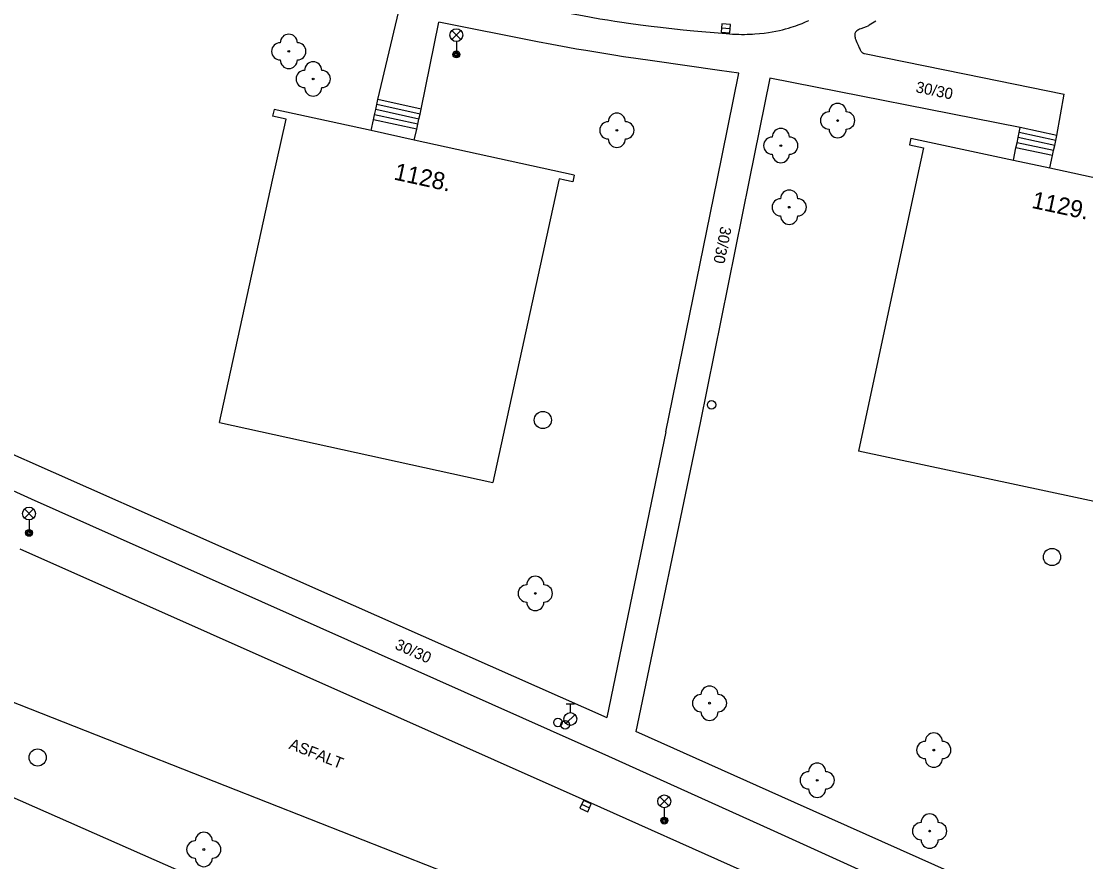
# Model space of a CAD drawing. Extents: x -538441 to -536770, y -1181008 to -1179809.
# Drawn here: x -538284.9 to -538222.9, y -1180822.8 to -1180773.9 of the extents above; entities that cross this region are included whole.
import ezdxf

# ---------------------------------------------------------------- set-up
doc = ezdxf.new("R2010")
doc.units = 0
for name, color, linetype in [('Vrstva 10', 7, 'Continuous'), ('Vrstva 11', 7, 'Continuous'), ('Vrstva 22', 7, 'Continuous'), ('Vrstva 27', 7, 'Continuous'), ('Vrstva 28', 7, 'Continuous'), ('Vrstva 33', 7, 'Continuous'), ('Vrstva 40', 7, 'Continuous'), ('Vrstva 47', 7, 'Continuous'), ('Vrstva 5', 7, 'Continuous')]:
    doc.layers.add(name, color=color, linetype=linetype)

msp = doc.modelspace()

# ---------------------------------------------------------------- linework, layer by layer
at = {"layer": 'Vrstva 10'}
for p, q in [((-538249.548, -1180773.977), (-538248.837, -1180774.075)), ((-538284.99, -1180804.6), (-538268.454, -1180811.952)), ((-538277.975, -1180816.445), (-538297.92, -1180808.6)), ((-538268.454, -1180811.952), (-538251.92, -1180819.31)), ((-538258.03, -1180824.29), (-538277.975, -1180816.445)), ((-538251.92, -1180819.31), (-538242.888, -1180823.336))]:
    msp.add_line(p, q, dxfattribs=at)
for points in [[(-538258.788, -1180772.341), (-538258.382, -1180772.429), (-538258.001, -1180772.508), (-538257.642, -1180772.58), (-538256.969, -1180772.709), (-538256.379, -1180772.817), (-538255.343, -1180772.998), (-538253.787, -1180773.264), (-538253.008, -1180773.399), (-538252.23, -1180773.54), (-538251.709, -1180773.634), (-538251.22, -1180773.719), (-538250.761, -1180773.794), (-538250.331, -1180773.862), (-538249.927, -1180773.923), (-538249.548, -1180773.977)], [(-538248.837, -1180774.075), (-538248.215, -1180774.155), (-538247.671, -1180774.22), (-538247.194, -1180774.275), (-538246.36, -1180774.364), (-538245.734, -1180774.426), (-538245.266, -1180774.47), (-538244.562, -1180774.532), (-538243.86, -1180774.59), (-538243.666, -1180774.604), (-538243.479, -1180774.615), (-538243.298, -1180774.623), (-538243.122, -1180774.628), (-538242.953, -1180774.63), (-538242.788, -1180774.63), (-538242.629, -1180774.627), (-538242.475, -1180774.623), (-538242.326, -1180774.616), (-538242.182, -1180774.607), (-538241.903, -1180774.585), (-538241.642, -1180774.557), (-538241.397, -1180774.524), (-538241.168, -1180774.486), (-538240.954, -1180774.446), (-538240.754, -1180774.403), (-538240.566, -1180774.359), (-538240.39, -1180774.313), (-538240.226, -1180774.267), (-538240.072, -1180774.22), (-538239.928, -1180774.173), (-538239.793, -1180774.127), (-538239.667, -1180774.081), (-538239.43, -1180773.99), (-538239.223, -1180773.903), (-538239.043, -1180773.821)]]:
    msp.add_lwpolyline(points, dxfattribs=at)
at = {"layer": 'Vrstva 11'}
for p, q in [((-538264.14, -1180778.43), (-538262.92, -1180773.28)), ((-538261.622, -1180778.982), (-538260.6, -1180773.92)), ((-538254.838, -1180775.066), (-538260.6, -1180773.92)), ((-538235.8, -1180775.75), (-538229.98, -1180776.935)), ((-538244.387, -1180783.117), (-538243.12, -1180776.89)), ((-538241.31, -1180777.19), (-538242.506, -1180783.117)), ((-538226.72, -1180780.06), (-538241.31, -1180777.19)), ((-538229.98, -1180776.935), (-538224.16, -1180778.12)), ((-538261.622, -1180778.982), (-538264.14, -1180778.43)), ((-538224.593, -1180780.515), (-538224.16, -1180778.12)), ((-538261.75, -1180779.568), (-538264.268, -1180779.016)), ((-538261.686, -1180779.275), (-538264.204, -1180778.723)), ((-538261.878, -1180780.154), (-538264.396, -1180779.602)), ((-538261.814, -1180779.861), (-538264.332, -1180779.309)), ((-538224.593, -1180780.515), (-538226.72, -1180780.06)), ((-538224.781, -1180781.395), (-538226.908, -1180780.94)), ((-538224.718, -1180781.101), (-538226.845, -1180780.646)), ((-538224.655, -1180780.808), (-538226.782, -1180780.353)), ((-538224.844, -1180781.688), (-538226.971, -1180781.233)), ((-538247.37, -1180797.77), (-538244.387, -1180783.117)), ((-538242.506, -1180783.117), (-538245.36, -1180797.26)), ((-538296.641, -1180794.101), (-538283.06, -1180800.13)), ((-538296.73, -1180796.15), (-538284.33, -1180801.67)), ((-538245.36, -1180797.26), (-538249.11, -1180815.22)), ((-538247.37, -1180797.77), (-538250.81, -1180814.42)), ((-538283.06, -1180800.13), (-538266.936, -1180807.277)), ((-538284.33, -1180801.67), (-538267.518, -1180809.165)), ((-538266.936, -1180807.277), (-538250.81, -1180814.42)), ((-538267.518, -1180809.165), (-538250.71, -1180816.67)), ((-538239.865, -1180819.36), (-538249.11, -1180815.22)), ((-538250.71, -1180816.67), (-538241.284, -1180820.915)), ((-538230.62, -1180823.5), (-538239.865, -1180819.36)), ((-538241.284, -1180820.915), (-538231.87, -1180825.19))]:
    msp.add_line(p, q, dxfattribs=at)
for points in [[(-538235.562, -1180774.13), (-538235.606, -1180774.153), (-538235.693, -1180774.191), (-538236.011, -1180774.303), (-538236.088, -1180774.335), (-538236.143, -1180774.362), (-538236.182, -1180774.385), (-538236.238, -1180774.424), (-538236.265, -1180774.446), (-538236.29, -1180774.47), (-538236.318, -1180774.504), (-538236.338, -1180774.538), (-538236.351, -1180774.573), (-538236.36, -1180774.607)], [(-538235.134, -1180773.862), (-538235.327, -1180773.981), (-538235.517, -1180774.103), (-538235.562, -1180774.13)], [(-538236.36, -1180774.607), (-538236.364, -1180774.64), (-538236.365, -1180774.672), (-538236.364, -1180774.704), (-538236.357, -1180774.763), (-538236.346, -1180774.817), (-538236.333, -1180774.865), (-538236.304, -1180774.948), (-538236.28, -1180775.009), (-538236.24, -1180775.098), (-538236.22, -1180775.14), (-538236.2, -1180775.18), (-538236.162, -1180775.263), (-538236.097, -1180775.419), (-538236.071, -1180775.476), (-538236.047, -1180775.525), (-538236.024, -1180775.566), (-538236.003, -1180775.599), (-538235.983, -1180775.627), (-538235.945, -1180775.67), (-538235.913, -1180775.698), (-538235.888, -1180775.715), (-538235.868, -1180775.727), (-538235.835, -1180775.74), (-538235.8, -1180775.75)], [(-538252.567, -1180775.487), (-538253.071, -1180775.397), (-538254.014, -1180775.223), (-538254.838, -1180775.066)], [(-538243.12, -1180776.89), (-538244.234, -1180776.729), (-538248.137, -1180776.181), (-538249.111, -1180776.04), (-538249.842, -1180775.931), (-538250.39, -1180775.846), (-538251.21, -1180775.716), (-538252.03, -1180775.58), (-538252.567, -1180775.487)], [(-538264.536, -1180780.238), (-538264.396, -1180779.602), (-538264.332, -1180779.309), (-538264.268, -1180779.016), (-538264.204, -1180778.723), (-538264.14, -1180778.43)], [(-538262.018, -1180780.79), (-538261.878, -1180780.154), (-538261.814, -1180779.861), (-538261.75, -1180779.568), (-538261.686, -1180779.275), (-538261.622, -1180778.982)], [(-538227.125, -1180781.956), (-538226.971, -1180781.233), (-538226.908, -1180780.94), (-538226.845, -1180780.646), (-538226.782, -1180780.353), (-538226.72, -1180780.06)], [(-538224.998, -1180782.411), (-538224.844, -1180781.688), (-538224.781, -1180781.395), (-538224.718, -1180781.101), (-538224.655, -1180780.808), (-538224.593, -1180780.515)]]:
    msp.add_lwpolyline(points, dxfattribs=at)
at = {"layer": 'Vrstva 22'}
for centre in [(-538269.33, -1180775.62), (-538267.91, -1180777.23), (-538237.36, -1180779.65), (-538250.22, -1180780.22), (-538240.67, -1180781.11), (-538240.18, -1180784.7), (-538254.97, -1180807.19), (-538244.82, -1180813.58), (-538231.76, -1180816.31), (-538238.55, -1180818.07), (-538232, -1180821.03), (-538274.28, -1180822.1)]:
    msp.add_circle(centre, 0.05, dxfattribs=at)
for centre, start, end in [((-538269.33, -1180775.12), 0, 180), ((-538269.83, -1180775.62), 90, 270), ((-538268.83, -1180775.62), 270, 90), ((-538269.33, -1180776.12), 180, 0), ((-538267.91, -1180776.73), 0, 180), ((-538268.41, -1180777.23), 90, 270), ((-538267.41, -1180777.23), 270, 90), ((-538267.91, -1180777.73), 180, 0), ((-538237.36, -1180779.15), 0, 180), ((-538250.22, -1180779.72), 0, 180), ((-538237.86, -1180779.65), 90, 270), ((-538236.86, -1180779.65), 270, 90), ((-538250.72, -1180780.22), 90, 270), ((-538249.72, -1180780.22), 270, 90), ((-538240.67, -1180780.61), 0, 180), ((-538237.36, -1180780.15), 180, 0), ((-538250.22, -1180780.72), 180, 0), ((-538241.17, -1180781.11), 90, 270), ((-538240.17, -1180781.11), 270, 90), ((-538240.67, -1180781.61), 180, 0), ((-538240.18, -1180784.2), 0, 180), ((-538240.68, -1180784.7), 90, 270), ((-538239.68, -1180784.7), 270, 90), ((-538240.18, -1180785.2), 180, 0), ((-538254.97, -1180806.69), 0, 180), ((-538255.47, -1180807.19), 90, 270), ((-538254.47, -1180807.19), 270, 90), ((-538254.97, -1180807.69), 180, 0), ((-538245.32, -1180813.58), 90, 270), ((-538244.82, -1180813.08), 0, 180), ((-538244.32, -1180813.58), 270, 90), ((-538244.82, -1180814.08), 180, 0), ((-538231.76, -1180815.81), 0, 180), ((-538232.26, -1180816.31), 90, 270), ((-538231.26, -1180816.31), 270, 90), ((-538231.76, -1180816.81), 180, 0), ((-538238.55, -1180817.57), 0, 180), ((-538239.05, -1180818.07), 90, 270), ((-538238.05, -1180818.07), 270, 90), ((-538238.55, -1180818.57), 180, 0), ((-538232.5, -1180821.03), 90, 270), ((-538232, -1180820.53), 0, 180), ((-538231.5, -1180821.03), 270, 90), ((-538274.28, -1180821.6), 0, 180), ((-538274.78, -1180822.1), 90, 270), ((-538273.78, -1180822.1), 270, 90), ((-538232, -1180821.53), 180, 0), ((-538274.28, -1180822.6), 180, 0)]:
    msp.add_arc(centre, 0.5, start, end, dxfattribs=at)
at = {"layer": 'Vrstva 27'}
for p, q in [((-538243.619, -1180774.3), (-538244.117, -1180774.262)), ((-538252.274, -1180819.467), (-538251.818, -1180819.671))]:
    msp.add_line(p, q, dxfattribs=at)
for points in [[(-538243.6, -1180774.051), (-538244.098, -1180774.013), (-538244.136, -1180774.511), (-538243.638, -1180774.549)], [(-538252.376, -1180819.696), (-538251.919, -1180819.899), (-538251.716, -1180819.442), (-538252.173, -1180819.239)]]:
    msp.add_lwpolyline(points, close=True, dxfattribs=at)
for centre in [(-538254.53, -1180797.09), (-538224.87, -1180805.07), (-538283.96, -1180816.74)]:
    msp.add_circle(centre, 0.5, dxfattribs=at)
at = {"layer": 'Vrstva 28'}
for p, q in [((-538253.18, -1180813.625), (-538252.68, -1180813.625)), ((-538252.93, -1180814.125), (-538252.93, -1180813.625)), ((-538253.188, -1180814.772), (-538252.658, -1180814.242))]:
    msp.add_line(p, q, dxfattribs=at)
for centre, radius in [((-538244.7, -1180796.21), 0.25), ((-538252.93, -1180814.5), 0.375), ((-538253.65, -1180814.7), 0.25), ((-538253.23, -1180814.84), 0.25)]:
    msp.add_circle(centre, radius, dxfattribs=at)
at = {"layer": 'Vrstva 33'}
for p, q in [((-538259.835, -1180774.94), (-538259.305, -1180774.41)), ((-538259.835, -1180774.41), (-538259.305, -1180774.94)), ((-538259.57, -1180775.05), (-538259.57, -1180775.8)), ((-538284.725, -1180802.8), (-538284.195, -1180802.27)), ((-538284.725, -1180802.27), (-538284.195, -1180802.8)), ((-538284.46, -1180802.91), (-538284.46, -1180803.66)), ((-538247.725, -1180819.56), (-538247.195, -1180819.03)), ((-538247.725, -1180819.03), (-538247.195, -1180819.56)), ((-538247.46, -1180819.67), (-538247.46, -1180820.42))]:
    msp.add_line(p, q, dxfattribs=at)
for centre, radius in [((-538259.57, -1180774.675), 0.375), ((-538259.57, -1180775.8), 0.2), ((-538259.57, -1180775.8), 0.145), ((-538259.57, -1180775.8), 0.0876), ((-538284.46, -1180802.535), 0.375), ((-538284.46, -1180803.66), 0.2), ((-538284.46, -1180803.66), 0.145), ((-538284.46, -1180803.66), 0.0876), ((-538247.46, -1180819.295), 0.375), ((-538247.46, -1180820.42), 0.2), ((-538247.46, -1180820.42), 0.145), ((-538247.46, -1180820.42), 0.0876)]:
    msp.add_circle(centre, radius, dxfattribs=at)
at = {"layer": 'Vrstva 5'}
for p, q in [((-538270.19, -1180779), (-538270.275, -1180779.39)), ((-538264.536, -1180780.238), (-538270.19, -1180779)), ((-538269.493, -1180779.561), (-538270.275, -1180779.39)), ((-538270.272, -1180783.117), (-538269.493, -1180779.561)), ((-538262.018, -1180780.79), (-538264.536, -1180780.238)), ((-538252.7, -1180782.83), (-538262.018, -1180780.79)), ((-538233.09, -1180780.68), (-538233.173, -1180781.071)), ((-538233.173, -1180781.071), (-538232.364, -1180781.244)), ((-538232.364, -1180781.244), (-538232.765, -1180783.117)), ((-538273.367, -1180797.243), (-538270.272, -1180783.117)), ((-538253.592, -1180783.117), (-538257.45, -1180800.73)), ((-538253.577, -1180783.047), (-538253.592, -1180783.117)), ((-538253.257, -1180783.117), (-538253.577, -1180783.047)), ((-538252.785, -1180783.22), (-538253.257, -1180783.117)), ((-538252.763, -1180783.117), (-538252.785, -1180783.22)), ((-538252.7, -1180782.83), (-538252.763, -1180783.117)), ((-538232.765, -1180783.117), (-538236.14, -1180798.9)), ((-538273.367, -1180797.243), (-538257.45, -1180800.73)), ((-538220.153, -1180802.32), (-538236.14, -1180798.9)), ((-538298.62, -1180813.24), (-538223.82, -1180846.17))]:
    msp.add_line(p, q, dxfattribs=at)
msp.add_lwpolyline([(-538233.09, -1180780.68), (-538227.125, -1180781.956), (-538224.998, -1180782.411), (-538221.696, -1180783.117)], dxfattribs=at)

# ---------------------------------------------------------------- texts
at = {"layer": 'Vrstva 40'}
for s, rotation, p in [('30/30', 348.49142, (-538232.85, -1180777.996)), ('30/30', 258.49495, (-538244.169, -1180785.774)), ('30/30', 335.94051, (-538263.2, -1180810.395)), ('ASFALT', 338.52871, (-538269.369, -1180816.213))]:
    msp.add_text(s, height=0.65, rotation=rotation, dxfattribs=at).set_placement(p)
at = {"layer": 'Vrstva 47'}
for s, rotation, p in [('1128.', 347.64821, (-538263.257, -1180783.077)), ('1129.', 347.9275, (-538226.105, -1180784.731))]:
    msp.add_text(s, height=1, rotation=rotation, dxfattribs=at).set_placement(p)

doc.saveas('drawing.dxf')
